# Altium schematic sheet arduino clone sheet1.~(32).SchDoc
size A; SheetNumber: 1; SheetTotal: 2
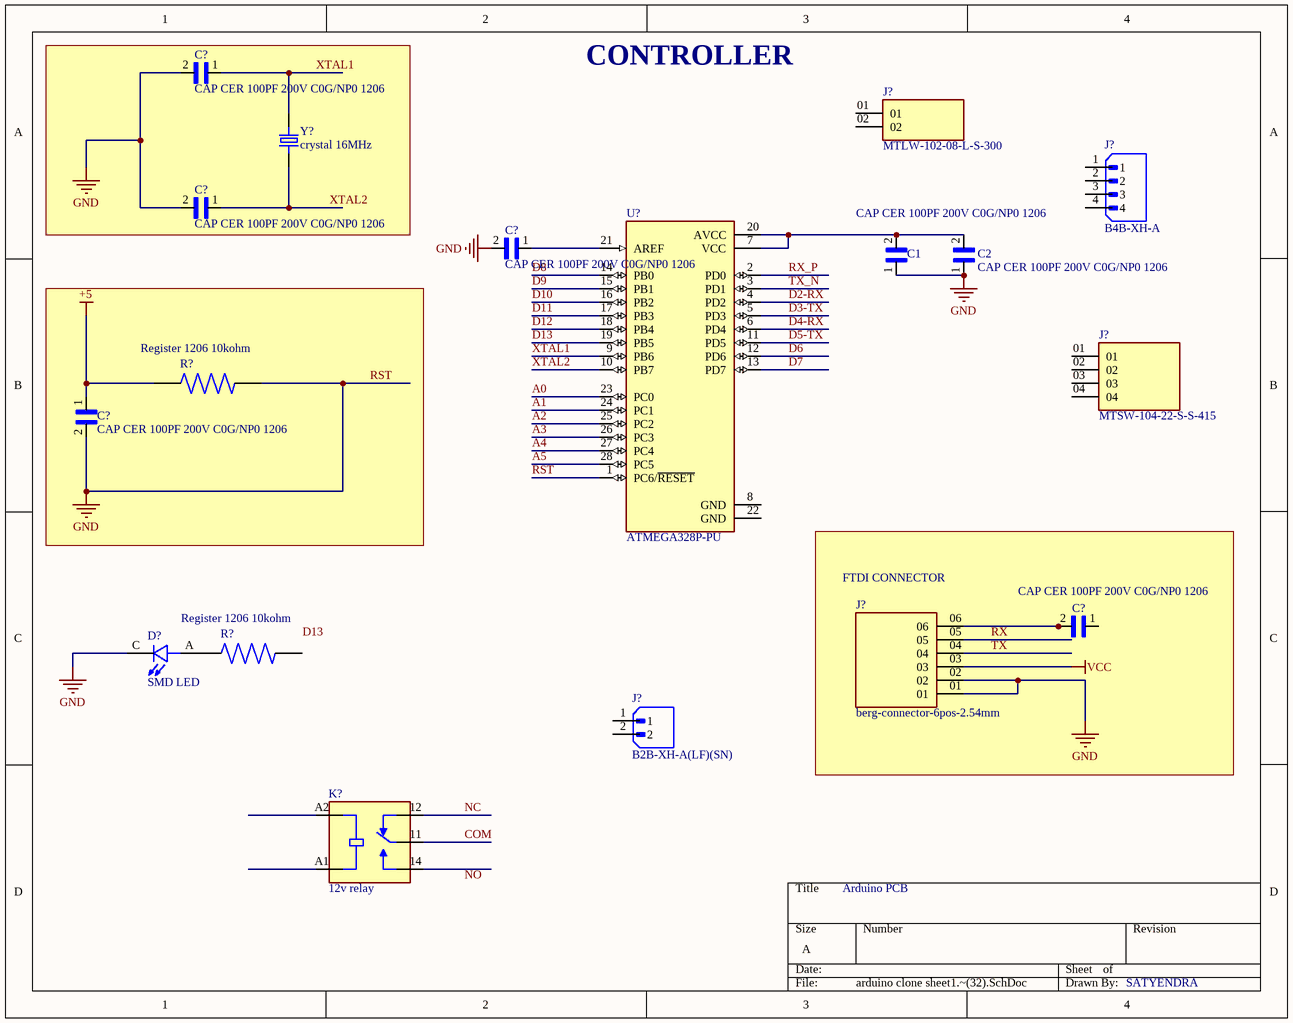
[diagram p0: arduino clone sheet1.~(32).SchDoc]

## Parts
(Parts that share a designator on the sheet are numbered #1, #2 ... from top to bottom, then left to right.)
C1  CAP CER 100PF 200V C0G/NP0 1206  [CAPC3216X88N]
C2  CAP CER 100PF 200V C0G/NP0 1206  [CAPC3216X88N]
C?#1  CAP CER 100PF 200V C0G/NP0 1206  [CAPC3216X88N]
C?#2  CAP CER 100PF 200V C0G/NP0 1206  [CAPC3216X88N]
C?#3  CAP CER 100PF 200V C0G/NP0 1206  [CAPC3216X88N]
C?#4  CAP CER 100PF 200V C0G/NP0 1206  [CAPC3216X88N]
C?#5  CAP CER 100PF 200V C0G/NP0 1206  [CAPC3216X88N]
D?  SMD LED  [LED_BR1102W-TR]
J?#1  MTLW-102-08-L-S-300  [SAMTEC_MTLW-102-08-L-S-300]
J?#2  B4B-XH-A  [JST_B4B-XH-A]
J?#3  MTSW-104-22-S-S-415  [SAMTEC_MTSW-104-22-S-S-415]
J?#4  berg-connector-6pos-2.54mm  [SAMTEC_SSQ-106-02-G-S-LL]
J?#5  B2B-XH-A(LF)(SN)  [JST_B2B-XH-A(LF)(SN)]
K?  12v relay  [RELAY_833H-1C-S-12VDC]
R?#1  Register 1206 10kohm  [RESC3015X65N]
R?#2  Register 1206 10kohm  [RESC3015X65N]
U?  ATMEGA328P-PU  [DIP794W46P254L2967H457Q28B]
Y?  crystal 16MHz  [XTAL_ECS-160-20-5PX-TR]

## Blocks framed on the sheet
FTDI CONNECTOR: C?#5 J?#4

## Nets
+5: C?#4.1 R?#1.1
RST: C1.1 C2.1 C?#1.2 C?#2.2 C?#3.2 C?#4.2 D?.C J?#4.01 J?#4.02 R?#1.2 U?.1(PC6/~{RESET})  [also labelled GND]
VCC: J?#4.03
A0: U?.23(PC0)
A1: U?.24(PC1)
A2: U?.25(PC2)
A3: U?.26(PC3)
A4: U?.27(PC4)
A5: U?.28(PC5)
COM: K?.11(COM)
D2-RX: U?.4(PD2)
D3-TX: U?.5(PD3)
D4-RX: U?.6(PD4)
D5-TX: U?.11(PD5)
D6: U?.12(PD6)
D7: U?.13(PD7)
D8: U?.14(PB0)
D9: U?.15(PB1)
D10: U?.16(PB2)
D11: U?.17(PB3)
D12: U?.18(PB4)
D13: U?.19(PB5)
NC: K?.12(NC)
RX: J?#4.05
RX_P: U?.2(PD0)
TX: J?#4.04
TX_N: U?.3(PD1)
XTAL1: C?#1.1 U?.9(PB6) Y?.2
XTAL2: C?#2.1 U?.10(PB7) Y?.1
NetC1_2: C1.2 C2.2 U?.7(VCC) U?.20(AVCC)
NetC?#3_1: C?#3.1 U?.21(AREF)
NetC?#5_2: C?#5.2 J?#4.06
NetD?_A: D?.A R?#2.1

Not connected (* = marked no-connect by the designer): C?#5 1; J?#1 01 02; J?#2 1 2 3 4; J?#3 01 02 03 04; J?#5 1 2; K? 14(NO) A1(COIL2) A2(COIL1); R?#2 2; U? 8(GND) 22(GND)

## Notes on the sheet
- CONTROLLER
- Arduino PCB
- SATYENDRA
- Labels drawn without touching a wire or pin: D13, NO

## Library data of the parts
C1 C2 C?#1-C?#5 = C1206C101J2GACTU
D? = BR1102W-TR: LED Uni-Color Red 660nm 2-Pin SMD T/R
J?#2 = B4B-XH-A: Connector Header Through Hole 4 position 0.098 (2.50mm); MF: JST Sales
J?#4 = berg-connector-6pos-2.54mm: MF: Samtec; MP: SSQ-106-02-G-S-LL
J?#5 = B2B-XH-A(LF)(SN): Connector Header Through Hole 2 position 0.098 (2.50mm); MF: JST Sales
K? = 833H-1C-S-12VDC: 833H Series 10 A SPDT 12 VDC Through Hole Miniature Sugar Cube Power Relay; MF: Song Chuan
R?#1 R?#2 = Register 1206 10kohm: MP: RNCF1206BKY10K0
U? = ATMEGA328P-PU: ATmega Series 20 MHz 32 KB Flash 2 KB SRAM 8-Bit Microcontroller - DIP-28
Y? = ECS-160-20-5PX-TR: 16 MHz Â±30ppm Crystal 20pF 40 Ohms HC-49/US; MF: ECS Inc.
